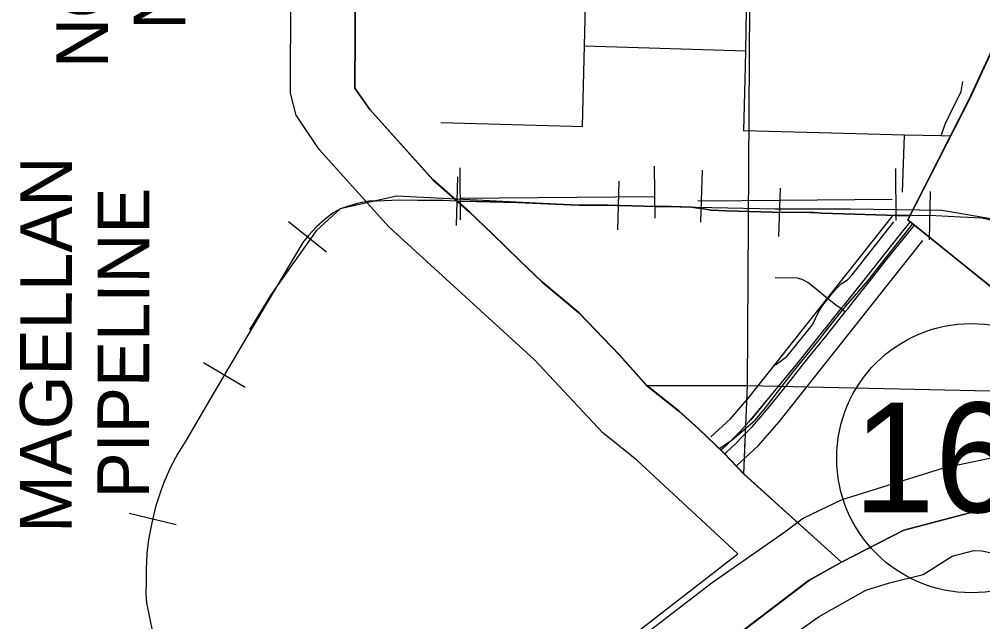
# Model space of a CAD drawing. Extents: x -132.8 to -73.3, y -60 to -26.
# Drawn here: x -126.937 to -125.444, y -48.564 to -47.631 of the extents above; entities that cross this region are included whole.
import ezdxf

# ---------------------------------------------------------------- set-up
doc = ezdxf.new("R2010")
doc.units = 0
for name, color, linetype in [('tdCoCityStreetMajor', 7, 'Continuous'), ('tdCoCityStreetMinor', 7, 'Continuous'), ('tdCoClipBndry', 7, 'Continuous'), ('tdCoCoBndry', 7, 'Continuous'), ('tdCoCorpBndry', 7, 'Continuous'), ('tdCoDivCarto', 7, 'Continuous'), ('tdCoHydroRiver', 7, 'Continuous'), ('tdCoPipe', 7, 'Continuous'), ('tdCoPipeTxt', 7, 'Continuous'), ('tdCoPriCL', 7, 'Continuous'), ('tdCoPriDiv', 7, 'Continuous'), ('tdCoPrimary', 7, 'Continuous'), ('tdCoRRCL', 7, 'Continuous'), ('tdCoSectLine', 7, 'Continuous'), ('tdCoSectLinePart', 7, 'Continuous'), ('tdCoShieldStRte', 7, 'Continuous'), ('tdCoStBndry', 7, 'Continuous'), ('tdCoStBndryPart', 7, 'Continuous'), ('tdCoTwpBndryShd', 7, 'Continuous')]:
    doc.layers.add(name, color=color, linetype=linetype)

msp = doc.modelspace()

# ---------------------------------------------------------------- linework, layer by layer
at = {"layer": 'tdCoCityStreetMajor'}
for points in [[(-125.4939, -47.812), (-125.5087, -47.8116), (-125.5655, -47.8102), (-125.6976, -47.8069), (-125.814, -47.8037), (-125.8116, -47.7041), (-125.8111, -47.6795), (-125.81, -47.6165), (-125.8096, -47.5909), (-125.8085, -47.5538)], [(-126.2833, -47.7905), (-126.0804, -47.7963), (-126.0642, -47.7968)]]:
    msp.add_lwpolyline(points, dxfattribs=at)
at = {"layer": 'tdCoCityStreetMinor'}
for p, q in [((-126.0611, -47.6719), (-126.0596, -47.6093)), ((-126.0611, -47.6719), (-125.8111, -47.6795)), ((-125.5685, -47.8986), (-125.5655, -47.8102))]:
    msp.add_line(p, q, dxfattribs=at)
for points in [[(-126.0642, -47.7968), (-126.0621, -47.7128), (-126.0611, -47.6719)], [(-125.5087, -47.8116), (-125.5022, -47.7932), (-125.4961, -47.7802), (-125.4773, -47.7425), (-125.4751, -47.7273)], [(-125.6838, -48.064), (-125.6719, -48.0495), (-125.6636, -48.0406), (-125.6537, -48.0344), (-125.6462, -48.0267), (-125.5816, -47.9447)], [(-125.6838, -48.064), (-125.705, -48.0464), (-125.7149, -48.0386), (-125.7227, -48.0344), (-125.731, -48.0318), (-125.7657, -48.0313)], [(-125.7652, -48.1662), (-125.7476, -48.1532), (-125.7341, -48.1366), (-125.7123, -48.1096), (-125.7088, -48.1052), (-125.7071, -48.1029), (-125.6988, -48.0853), (-125.6931, -48.0759), (-125.6838, -48.064)], [(-125.657, -48.0842), (-125.6638, -48.079), (-125.672, -48.0729), (-125.6838, -48.064)]]:
    msp.add_lwpolyline(points, dxfattribs=at)
at = {"layer": 'tdCoClipBndry'}
msp.add_lwpolyline([(-125.699, -51.5184), (-125.6517, -51.3639), (-125.6445, -51.2613), (-125.6373, -50.967), (-125.6719, -50.7936), (-125.7408, -50.527), (-126.0038, -49.7931), (-126.103, -49.4235), (-126.1357, -49.2006), (-126.133, -49.0767), (-126.1222, -48.9873), (-126.1187, -48.8646), (-126.0876, -48.7442), (-126.0156, -48.6142), (-125.9752, -48.5766), (-125.8237, -48.4588), (-125.9799, -48.3137), (-126.0327, -48.2713), (-126.1387, -48.1584), (-126.3641, -47.9525), (-126.472, -47.8327), (-126.5077, -47.7794), (-126.5166, -47.7455), (-126.516, -47.5917)], dxfattribs=at)
at = {"layer": 'tdCoCoBndry'}
for p, q in [((-126.4166, -47.7373), (-126.4155, -47.5684)), ((-125.4291, -47.6777), (-125.4646, -47.7544)), ((-126.3933, -47.7706), (-126.4166, -47.7373)), ((-125.4646, -47.7544), (-125.5599, -47.9415)), ((-126.2954, -47.8795), (-126.3933, -47.7706)), ((-126.2392, -47.9289), (-126.2954, -47.8795)), ((-126.2037, -47.9634), (-126.2392, -47.9289)), ((-125.5599, -47.9415), (-125.3602, -48.1019)), ((-126.1612, -48.0043), (-126.2037, -47.9634)), ((-126.1262, -48.0382), (-126.1612, -48.0043)), ((-126.0695, -48.0857), (-126.1262, -48.0382)), ((-126.0064, -48.1511), (-126.0695, -48.0857)), ((-125.9645, -48.1979), (-126.0064, -48.1511)), ((-125.9143, -48.2379), (-125.9645, -48.1979)), ((-125.8841, -48.2654), (-125.9143, -48.2379)), ((-125.8447, -48.303), (-125.8841, -48.2654)), ((-125.8138, -48.3352), (-125.8447, -48.303)), ((-125.6627, -48.4716), (-125.8138, -48.3352)), ((-125.7126, -48.4994), (-125.6627, -48.4716)), ((-125.7534, -48.5306), (-125.7126, -48.4994)), ((-125.8225, -48.5835), (-125.7534, -48.5306))]:
    msp.add_line(p, q, dxfattribs=at)
for points in [[(-126.4159, -47.5684), (-126.417, -47.7373), (-126.3937, -47.7706), (-126.2957, -47.8795), (-126.2396, -47.9289), (-126.204, -47.9634), (-126.1616, -48.0043), (-126.1266, -48.0382), (-126.0698, -48.0857), (-126.0068, -48.1511), (-125.9649, -48.1979), (-125.9146, -48.2379), (-125.8845, -48.2654), (-125.8451, -48.303), (-125.8141, -48.3352), (-125.6631, -48.4716), (-125.713, -48.4994), (-125.7538, -48.5306), (-125.8229, -48.5835)], [(-125.8225, -48.5835), (-125.7534, -48.5306), (-125.7126, -48.4994), (-125.6627, -48.4716), (-125.8138, -48.3352), (-125.8447, -48.303), (-125.8841, -48.2654), (-125.9143, -48.2379), (-125.9645, -48.1979), (-126.0064, -48.1511), (-126.0695, -48.0857), (-126.1262, -48.0382), (-126.1612, -48.0043), (-126.2037, -47.9634), (-126.2392, -47.9289), (-126.2954, -47.8795), (-126.3933, -47.7706), (-126.4166, -47.7373), (-126.4155, -47.5684)], [(-125.3606, -48.1019), (-125.5603, -47.9415), (-125.465, -47.7544), (-125.4295, -47.6777)], [(-125.4291, -47.6777), (-125.4646, -47.7544), (-125.5599, -47.9415), (-125.3602, -48.1019)]]:
    msp.add_lwpolyline(points, dxfattribs=at)
at = {"layer": 'tdCoCorpBndry'}
for points in [[(-125.2042, -48.3274), (-125.5661, -48.422), (-125.6627, -48.4716), (-125.8138, -48.3352), (-125.8447, -48.303), (-125.8841, -48.2654), (-125.9143, -48.2379), (-125.9645, -48.1979), (-126.0064, -48.1511), (-126.0695, -48.0857), (-126.1262, -48.0382), (-126.1612, -48.0043), (-126.2037, -47.9634), (-126.2392, -47.9289), (-126.2954, -47.8795), (-126.3933, -47.7706), (-126.4166, -47.7373), (-126.4155, -47.5684)], [(-125.4291, -47.6777), (-125.4646, -47.7544), (-125.5599, -47.9415), (-125.3602, -48.1019)], [(-125.9359, -49.6595), (-125.9637, -49.5616), (-125.9808, -49.494), (-126.0044, -49.405), (-126.0111, -49.3695), (-126.0145, -49.3144), (-126.0261, -49.2469), (-126.0359, -49.1902), (-126.0327, -49.0795), (-126.0277, -49.0454), (-126.022, -48.9949), (-126.0189, -48.8748), (-125.9949, -48.7826), (-125.9861, -48.7649), (-125.964, -48.7263), (-125.9413, -48.6815), (-125.9135, -48.6555), (-125.8674, -48.6176), (-125.8225, -48.5835), (-125.7534, -48.5306), (-125.7126, -48.4994), (-125.6627, -48.4716), (-125.5661, -48.422), (-125.2042, -48.3274)]]:
    msp.add_lwpolyline(points, dxfattribs=at)
at = {"layer": 'tdCoDivCarto'}
for p, q in [((-125.5961, -48.0072), (-125.5498, -47.9496)), ((-125.5569, -47.945), (-125.5739, -47.966)), ((-125.5564, -47.9443), (-125.5569, -47.945)), ((-125.5564, -47.9443), (-125.5569, -47.945)), ((-125.5739, -47.966), (-125.6212, -48.0257)), ((-125.6199, -48.0374), (-125.5961, -48.0072)), ((-125.6212, -48.0257), (-125.6264, -48.0322)), ((-125.6264, -48.0322), (-125.6594, -48.0735)), ((-125.6264, -48.0322), (-125.6594, -48.0735)), ((-125.6446, -48.0686), (-125.6199, -48.0374)), ((-125.6594, -48.0735), (-125.6638, -48.079)), ((-125.6527, -48.0788), (-125.6446, -48.0686)), ((-125.6638, -48.079), (-125.6888, -48.1103)), ((-125.6833, -48.1173), (-125.657, -48.0842)), ((-125.657, -48.0842), (-125.6527, -48.0788)), ((-125.6901, -48.1119), (-125.7305, -48.1623)), ((-125.6888, -48.1103), (-125.6901, -48.1119)), ((-125.6873, -48.1223), (-125.6833, -48.1173)), ((-125.7142, -48.1546), (-125.6873, -48.1223)), ((-125.7305, -48.1623), (-125.7711, -48.2121)), ((-125.7477, -48.1976), (-125.7142, -48.1546)), ((-125.7724, -48.2279), (-125.7477, -48.1976)), ((-125.7711, -48.2121), (-125.8035, -48.2512)), ((-125.7845, -48.2429), (-125.7724, -48.2279)), ((-125.8035, -48.2512), (-125.8067, -48.255)), ((-125.8007, -48.2617), (-125.7845, -48.2429)), ((-125.8205, -48.2698), (-125.8422, -48.2915)), ((-125.8067, -48.255), (-125.8205, -48.2698)), ((-125.8168, -48.2777), (-125.8007, -48.2617)), ((-125.8279, -48.2895), (-125.8168, -48.2777)), ((-125.8422, -48.2915), (-125.8499, -48.298)), ((-125.8414, -48.3021), (-125.8279, -48.2895)), ((-125.8436, -48.3041), (-125.8414, -48.3021))]:
    msp.add_line(p, q, dxfattribs=at)
for points in [[(-125.5569, -47.945), (-125.5739, -47.966), (-125.6212, -48.0257), (-125.6264, -48.0322)], [(-125.5569, -47.945), (-125.5739, -47.966), (-125.6212, -48.0257), (-125.6264, -48.0322)], [(-125.5569, -47.945), (-125.5739, -47.966), (-125.6212, -48.0257), (-125.6264, -48.0322)], [(-125.6199, -48.0374), (-125.5961, -48.0072), (-125.5498, -47.9496)], [(-125.6199, -48.0374), (-125.5961, -48.0072), (-125.5498, -47.9496)], [(-125.6199, -48.0374), (-125.5961, -48.0072), (-125.5498, -47.9496)], [(-125.5564, -47.9443), (-125.5569, -47.945)], [(-125.5564, -47.9443), (-125.5569, -47.945)], [(-125.6264, -48.0322), (-125.6594, -48.0735)], [(-125.6264, -48.0322), (-125.6594, -48.0735)], [(-125.6527, -48.0788), (-125.6446, -48.0686), (-125.6199, -48.0374)], [(-125.6527, -48.0788), (-125.6446, -48.0686), (-125.6199, -48.0374)], [(-125.6527, -48.0788), (-125.6446, -48.0686), (-125.6199, -48.0374)], [(-125.6594, -48.0735), (-125.6638, -48.079), (-125.6888, -48.1103), (-125.6901, -48.1119)], [(-125.6594, -48.0735), (-125.6638, -48.079), (-125.6888, -48.1103), (-125.6901, -48.1119)], [(-125.6594, -48.0735), (-125.6638, -48.079), (-125.6888, -48.1103), (-125.6901, -48.1119)], [(-125.6833, -48.1173), (-125.657, -48.0842), (-125.6527, -48.0788)], [(-125.6833, -48.1173), (-125.657, -48.0842), (-125.6527, -48.0788)], [(-125.6833, -48.1173), (-125.657, -48.0842), (-125.6527, -48.0788)], [(-125.6901, -48.1119), (-125.7305, -48.1623), (-125.7711, -48.2121), (-125.8067, -48.255), (-125.8205, -48.2698), (-125.8422, -48.2915), (-125.8499, -48.298)], [(-125.6901, -48.1119), (-125.7305, -48.1623), (-125.7711, -48.2121), (-125.8067, -48.255), (-125.8205, -48.2698), (-125.8422, -48.2915), (-125.8499, -48.298)], [(-125.8436, -48.3041), (-125.8414, -48.3021), (-125.8279, -48.2895), (-125.8168, -48.2777), (-125.8007, -48.2617), (-125.7845, -48.2429), (-125.7724, -48.2279), (-125.7477, -48.1976), (-125.7142, -48.1546), (-125.6873, -48.1223), (-125.6833, -48.1173)], [(-125.8436, -48.3041), (-125.8414, -48.3021), (-125.8279, -48.2895), (-125.8168, -48.2777), (-125.8007, -48.2617), (-125.7845, -48.2429), (-125.7724, -48.2279), (-125.7477, -48.1976), (-125.7142, -48.1546), (-125.6873, -48.1223), (-125.6833, -48.1173)], [(-125.8436, -48.3041), (-125.8414, -48.3021), (-125.8279, -48.2895), (-125.8168, -48.2777), (-125.8007, -48.2617), (-125.7845, -48.2429), (-125.7724, -48.2279), (-125.7477, -48.1976), (-125.7142, -48.1546), (-125.6873, -48.1223), (-125.6833, -48.1173)], [(-125.6901, -48.1119), (-125.7305, -48.1623), (-125.7711, -48.2121), (-125.8035, -48.2512)], [(-125.8035, -48.2512), (-125.8067, -48.255), (-125.8205, -48.2698), (-125.8422, -48.2915), (-125.8499, -48.298)]]:
    msp.add_lwpolyline(points, dxfattribs=at)
at = {"layer": 'tdCoHydroRiver'}
for points in [[(-125.3665, -48.2971), (-125.5047, -48.3263), (-125.6623, -48.3754), (-125.7216, -48.4037), (-125.7506, -48.425), (-125.8633, -48.5038), (-125.9973, -48.6072)], [(-125.8102, -48.6347), (-125.6975, -48.5558), (-125.6253, -48.5153), (-125.5887, -48.5037), (-125.5362, -48.491), (-125.4912, -48.4623), (-125.4578, -48.4538), (-125.4452, -48.4542), (-125.3934, -48.4651)]]:
    msp.add_lwpolyline(points, dxfattribs=at)
at = {"layer": 'tdCoPipe'}
for points in [[(-126.253, -47.9414), (-126.2537, -47.8609)], [(-126.253, -47.9414), (-126.2537, -47.8609)], [(-125.9517, -47.9387), (-125.9524, -47.8581)], [(-125.9517, -47.9387), (-125.9524, -47.8581)], [(-125.8808, -47.9449), (-125.8798, -47.9117), (-125.8783, -47.8645)], [(-125.8808, -47.9449), (-125.8798, -47.9117), (-125.8783, -47.8645)], [(-125.5779, -47.9427), (-125.5787, -47.8621)], [(-125.5779, -47.9427), (-125.5787, -47.8621)], [(-126.2535, -47.9081), (-125.9523, -47.9054)], [(-126.2535, -47.9081), (-125.9523, -47.9054)], [(-125.8853, -47.9117), (-125.8747, -47.912), (-125.5841, -47.9095)], [(-125.8853, -47.9117), (-125.8747, -47.912), (-125.5841, -47.9095)]]:
    msp.add_lwpolyline(points, dxfattribs=at)
at = {"layer": 'tdCoPriCL'}
msp.add_lwpolyline([(-125.8524, -48.2958), (-125.8324, -48.2822), (-125.8112, -48.2643), (-125.7964, -48.2516), (-125.7828, -48.2353), (-125.7375, -48.177), (-125.6977, -48.1271), (-125.6875, -48.1143), (-125.6611, -48.0814), (-125.6567, -48.0759), (-125.6223, -48.0358), (-125.5531, -47.9484)], dxfattribs=at)
at = {"layer": 'tdCoPriDiv'}
for points in [[(-125.8654, -48.2774), (-125.8347, -48.2496), (-125.8061, -48.2163), (-125.5837, -47.936)], [(-125.825, -48.3218), (-125.7917, -48.2915), (-125.7596, -48.2543), (-125.5367, -47.9733)]]:
    msp.add_lwpolyline(points, dxfattribs=at)
at = {"layer": 'tdCoPrimary'}
for p, q in [((-125.5564, -47.9443), (-125.5569, -47.945)), ((-125.5564, -47.9443), (-125.5569, -47.945)), ((-125.6264, -48.0322), (-125.6594, -48.0735)), ((-125.6264, -48.0322), (-125.6594, -48.0735))]:
    msp.add_line(p, q, dxfattribs=at)
for points in [[(-125.5564, -47.9443), (-125.5569, -47.945), (-125.5569, -47.945), (-125.5739, -47.966), (-125.6212, -48.0257), (-125.6264, -48.0322), (-125.6594, -48.0735), (-125.6638, -48.079), (-125.6888, -48.1103), (-125.6901, -48.1119), (-125.7305, -48.1623), (-125.7711, -48.2121), (-125.8035, -48.2512), (-125.8067, -48.255), (-125.8205, -48.2698), (-125.8422, -48.2915), (-125.8499, -48.298)], [(-125.8436, -48.3041), (-125.8414, -48.3021), (-125.8279, -48.2895), (-125.8168, -48.2777), (-125.8007, -48.2617), (-125.7845, -48.2429), (-125.7724, -48.2279), (-125.7477, -48.1976), (-125.7142, -48.1546), (-125.6873, -48.1223), (-125.6833, -48.1173), (-125.657, -48.0842), (-125.6527, -48.0788), (-125.6446, -48.0686), (-125.6199, -48.0374), (-125.5961, -48.0072), (-125.5498, -47.9496)], [(-125.5569, -47.945), (-125.5739, -47.966), (-125.6212, -48.0257), (-125.6264, -48.0322)], [(-125.5569, -47.945), (-125.5739, -47.966), (-125.6212, -48.0257), (-125.6264, -48.0322)], [(-125.6199, -48.0374), (-125.5961, -48.0072), (-125.5498, -47.9496)], [(-125.6199, -48.0374), (-125.5961, -48.0072), (-125.5498, -47.9496)], [(-125.6527, -48.0788), (-125.6446, -48.0686), (-125.6199, -48.0374)], [(-125.6527, -48.0788), (-125.6446, -48.0686), (-125.6199, -48.0374)], [(-125.6594, -48.0735), (-125.6638, -48.079), (-125.6888, -48.1103), (-125.6901, -48.1119)], [(-125.6594, -48.0735), (-125.6638, -48.079), (-125.6888, -48.1103), (-125.6901, -48.1119)], [(-125.6833, -48.1173), (-125.657, -48.0842), (-125.6527, -48.0788)], [(-125.6833, -48.1173), (-125.657, -48.0842), (-125.6527, -48.0788)], [(-125.8436, -48.3041), (-125.8414, -48.3021), (-125.8279, -48.2895), (-125.8168, -48.2777), (-125.8007, -48.2617), (-125.7845, -48.2429), (-125.7724, -48.2279), (-125.7477, -48.1976), (-125.7142, -48.1546), (-125.6873, -48.1223), (-125.6833, -48.1173)], [(-125.8436, -48.3041), (-125.8414, -48.3021), (-125.8279, -48.2895), (-125.8168, -48.2777), (-125.8007, -48.2617), (-125.7845, -48.2429), (-125.7724, -48.2279), (-125.7477, -48.1976), (-125.7142, -48.1546), (-125.6873, -48.1223), (-125.6833, -48.1173)], [(-125.6901, -48.1119), (-125.7305, -48.1623), (-125.7711, -48.2121), (-125.8035, -48.2512)], [(-125.6901, -48.1119), (-125.7305, -48.1623), (-125.7711, -48.2121), (-125.8035, -48.2512)], [(-125.8035, -48.2512), (-125.8067, -48.255), (-125.8205, -48.2698), (-125.8422, -48.2915), (-125.8499, -48.298)], [(-125.8035, -48.2512), (-125.8067, -48.255), (-125.8205, -48.2698), (-125.8422, -48.2915), (-125.8499, -48.298)]]:
    msp.add_lwpolyline(points, dxfattribs=at)
at = {"layer": 'tdCoRRCL'}
for p, q in [((-126.2591, -47.9501), (-126.2572, -47.8751)), ((-126.0093, -47.9568), (-126.0072, -47.8818)), ((-125.7598, -47.9671), (-125.7576, -47.8922)), ((-125.5254, -47.8976), (-125.527, -47.9726)), ((-125.7655, -47.925), (-126.0841, -47.9182)), ((-125.6487, -47.9249), (-125.7655, -47.925)), ((-126.5196, -47.9443), (-126.4609, -47.9909)), ((-126.6512, -48.1627), (-126.5866, -48.2008)), ((-126.7663, -48.3956), (-126.6934, -48.4133))]:
    msp.add_line(p, q, dxfattribs=at)
for points in [[(-126.2581, -47.9126), (-126.2805, -47.9115), (-126.3194, -47.9115), (-126.3475, -47.9111), (-126.3827, -47.9123), (-126.3952, -47.9126), (-126.411, -47.9159), (-126.4265, -47.9205), (-126.439, -47.9245), (-126.4505, -47.9304), (-126.4626, -47.9402), (-126.4755, -47.9517), (-126.4886, -47.9656), (-126.4975, -47.9767), (-126.5639, -48.0886), (-126.633, -48.2057), (-126.6781, -48.2826), (-126.6909, -48.3033), (-126.7021, -48.3247), (-126.7126, -48.3484), (-126.7185, -48.3642), (-126.7254, -48.3862), (-126.7314, -48.4106), (-126.7363, -48.4365), (-126.7389, -48.4582), (-126.7402, -48.4822), (-126.7402, -48.5007), (-126.7406, -48.5211), (-126.7397, -48.5349), (-126.7304, -48.5803)], [(-126.2581, -47.9126), (-126.2805, -47.9115), (-126.3194, -47.9115), (-126.3475, -47.9111), (-126.3827, -47.9123), (-126.3952, -47.9126), (-126.411, -47.9159), (-126.4265, -47.9205), (-126.439, -47.9245), (-126.4505, -47.9304), (-126.4626, -47.9402), (-126.4755, -47.9517), (-126.4886, -47.9656), (-126.4975, -47.9767), (-126.5639, -48.0886), (-126.633, -48.2057), (-126.6781, -48.2826), (-126.6909, -48.3033), (-126.7021, -48.3247), (-126.7126, -48.3484), (-126.7185, -48.3642), (-126.7254, -48.3862), (-126.7314, -48.4106), (-126.7363, -48.4365), (-126.7389, -48.4582), (-126.7402, -48.4822), (-126.7402, -48.5007), (-126.7406, -48.5211), (-126.7397, -48.5349), (-126.7304, -48.5803)], [(-126.0841, -47.9182), (-126.3521, -47.9048), (-126.4394, -47.9246)], [(-126.4394, -47.9246), (-126.4766, -47.9584), (-126.5471, -48.0575), (-126.5801, -48.1118)], [(-125.5567, -47.9345), (-125.5763, -47.9345), (-125.6935, -47.9312), (-125.7057, -47.9303), (-125.7107, -47.93), (-125.716, -47.9296), (-125.7515, -47.9299), (-125.8415, -47.9273), (-125.8648, -47.9265), (-125.8768, -47.9243), (-125.8951, -47.9219), (-125.9269, -47.9209), (-125.9512, -47.9209), (-126.0243, -47.9188), (-126.0698, -47.9186), (-126.1647, -47.9147), (-126.2283, -47.9133), (-126.2581, -47.9126)], [(-126.2581, -47.9126), (-126.2283, -47.9133), (-126.1647, -47.9147), (-126.0698, -47.9186), (-126.0243, -47.9188), (-125.9512, -47.9209), (-125.9269, -47.9209), (-125.8951, -47.9219), (-125.8768, -47.9243), (-125.8648, -47.9265), (-125.8415, -47.9273), (-125.7515, -47.9299), (-125.716, -47.9296), (-125.7107, -47.93), (-125.7057, -47.9303), (-125.6935, -47.9312), (-125.5763, -47.9345), (-125.5567, -47.9345)], [(-125.1474, -48.0674), (-125.2185, -48.0734), (-125.2593, -48.0645), (-125.298, -48.0351), (-125.3577, -47.9641), (-125.4109, -47.9437), (-125.5067, -47.927), (-125.6487, -47.9249)], [(-125.4224, -47.9442), (-125.4449, -47.9387), (-125.4783, -47.9374), (-125.5166, -47.9353), (-125.5567, -47.9345)], [(-125.4224, -47.9442), (-125.4449, -47.9387), (-125.4783, -47.9374), (-125.5166, -47.9353), (-125.5567, -47.9345)]]:
    msp.add_lwpolyline(points, dxfattribs=at)
at = {"layer": 'tdCoSectLine'}
for points in [[(-126.4116, -47.1636), (-126.4217, -47.3782), (-126.426, -47.5482), (-126.4159, -47.5684), (-126.417, -47.7373), (-126.3937, -47.7706), (-126.2957, -47.8795), (-126.2396, -47.9289), (-126.204, -47.9634), (-126.1616, -48.0043), (-126.1266, -48.0382), (-126.0698, -48.0857), (-126.0068, -48.1511), (-125.9649, -48.1979)], [(-125.8085, -48.1981), (-125.8021, -47.1857)], [(-125.2203, -48.2111), (-125.2949, -48.1537), (-125.3606, -48.1019), (-125.5603, -47.9415), (-125.465, -47.7544), (-125.4295, -47.6777), (-125.3621, -47.5459), (-125.2861, -47.3958), (-125.2282, -47.2723), (-125.196, -47.204)], [(-125.9649, -48.1979), (-125.8085, -48.1981)], [(-125.9649, -48.1979), (-125.9146, -48.2379), (-125.8845, -48.2654), (-125.8451, -48.303), (-125.8141, -48.3352)], [(-125.8141, -48.3352), (-125.8085, -48.1981)], [(-125.8085, -48.1981), (-125.2203, -48.2111)], [(-125.8141, -48.3352), (-125.6631, -48.4716), (-125.713, -48.4994), (-125.7538, -48.5306), (-125.8229, -48.5835)]]:
    msp.add_lwpolyline(points, dxfattribs=at)
at = {"layer": 'tdCoSectLinePart'}
for points in [[(-126.4116, -47.1636), (-126.4217, -47.3782), (-126.426, -47.5482), (-126.4159, -47.5684), (-126.417, -47.7373), (-126.3937, -47.7706), (-126.2957, -47.8795), (-126.2396, -47.9289), (-126.204, -47.9634), (-126.1616, -48.0043), (-126.1266, -48.0382), (-126.0698, -48.0857), (-126.0068, -48.1511), (-125.9649, -48.1979)], [(-125.2203, -48.2111), (-125.2949, -48.1537), (-125.3606, -48.1019), (-125.5603, -47.9415), (-125.465, -47.7544), (-125.4295, -47.6777), (-125.4222, -47.6635)], [(-125.9649, -48.1979), (-125.8934, -48.198)], [(-125.9649, -48.1979), (-125.9146, -48.2379), (-125.8845, -48.2654), (-125.8451, -48.303), (-125.8141, -48.3352)], [(-125.8141, -48.3352), (-125.812, -48.283)], [(-125.8141, -48.3352), (-125.6631, -48.4716), (-125.713, -48.4994), (-125.7382, -48.5187)]]:
    msp.add_lwpolyline(points, dxfattribs=at)
at = {"layer": 'tdCoShieldStRte'}
msp.add_circle((-125.4618, -48.3106), 0.2085, dxfattribs=at)
at = {"layer": 'tdCoStBndry'}
for points in [[(-126.4159, -47.5684), (-126.417, -47.7373), (-126.3937, -47.7706), (-126.2957, -47.8795), (-126.2396, -47.9289), (-126.204, -47.9634), (-126.1616, -48.0043), (-126.1266, -48.0382), (-126.0698, -48.0857), (-126.0068, -48.1511), (-125.9649, -48.1979), (-125.9146, -48.2379), (-125.8845, -48.2654), (-125.8451, -48.303), (-125.8141, -48.3352), (-125.6631, -48.4716), (-125.713, -48.4994), (-125.7538, -48.5306), (-125.8229, -48.5835)], [(-125.3606, -48.1019), (-125.5603, -47.9415), (-125.465, -47.7544), (-125.4295, -47.6777)]]:
    msp.add_lwpolyline(points, dxfattribs=at)
at = {"layer": 'tdCoStBndryPart'}
for points in [[(-126.4159, -47.5684), (-126.417, -47.7373), (-126.3937, -47.7706), (-126.2957, -47.8795), (-126.2396, -47.9289), (-126.204, -47.9634), (-126.1616, -48.0043), (-126.1266, -48.0382), (-126.0698, -48.0857), (-126.0068, -48.1511), (-125.9649, -48.1979), (-125.9146, -48.2379), (-125.8845, -48.2654), (-125.8451, -48.303), (-125.8141, -48.3352), (-125.6631, -48.4716), (-125.713, -48.4994), (-125.7382, -48.5187)], [(-125.1087, -48.3024), (-125.1205, -48.293), (-125.1629, -48.2616), (-125.1956, -48.2307), (-125.2203, -48.2111), (-125.2949, -48.1537), (-125.3606, -48.1019), (-125.5603, -47.9415), (-125.465, -47.7544), (-125.4295, -47.6777), (-125.4222, -47.6635)]]:
    msp.add_lwpolyline(points, dxfattribs=at)
at = {"layer": 'tdCoTwpBndryShd'}
for points in [[(-125.8229, -48.5835), (-125.7538, -48.5306), (-125.713, -48.4994), (-125.6631, -48.4716), (-125.8141, -48.3352), (-125.8451, -48.303), (-125.8845, -48.2654), (-125.9146, -48.2379), (-125.9649, -48.1979), (-126.0068, -48.1511), (-126.0698, -48.0857), (-126.1266, -48.0382), (-126.1616, -48.0043), (-126.204, -47.9634), (-126.2396, -47.9289), (-126.2957, -47.8795), (-126.3937, -47.7706), (-126.417, -47.7373), (-126.4159, -47.5684)], [(-125.4295, -47.6777), (-125.465, -47.7544), (-125.5603, -47.9415), (-125.3606, -48.1019)]]:
    msp.add_lwpolyline(points, dxfattribs=at)

# ---------------------------------------------------------------- texts
at = {"layer": 'tdCoPipeTxt'}
for s, p in [('NORTHERN ', (-126.7994, -47.7063)), ('NATURAL', (-126.6793, -47.647)), ('MAGELLAN', (-126.8556, -48.4263)), ('PIPELINE', (-126.7356, -48.3731))]:
    msp.add_text(s, height=0.08, rotation=89.9359, dxfattribs=at).set_placement(p)
at = {"layer": 'tdCoShieldStRte'}
msp.add_text('165', height=0.17, dxfattribs=at).set_placement((-125.6448, -48.3945))

doc.saveas('drawing.dxf')
